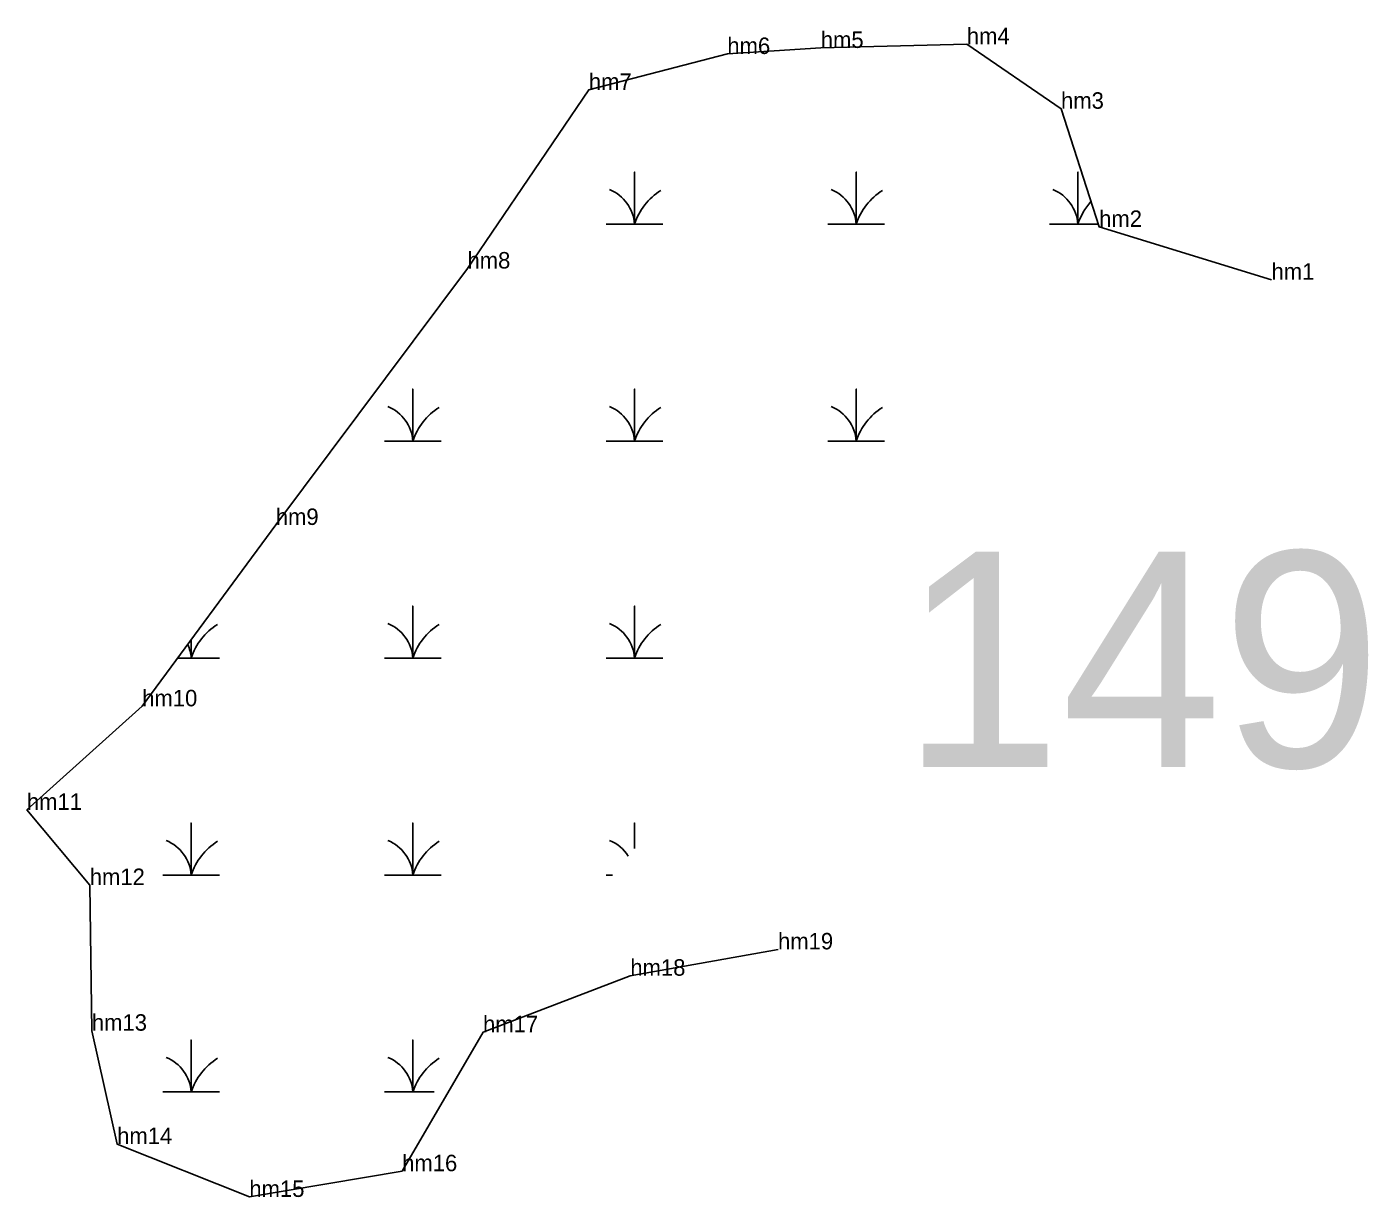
# Model space of a CAD drawing. Extents: x 2072529 to 2268796, y 436423 to 470406.
# Drawn here: x 2173124 to 2173530.9, y 447172.3 to 447527.2 of the extents above; entities that cross this region are included whole.
import ezdxf

# ---------------------------------------------------------------- set-up
doc = ezdxf.new("R2010")
doc.units = 0
for name, color, linetype in [('Default', 7, 'Continuous'), ('Exist Environmental Wetland Boundary Cogo Comment', 7, 'Continuous'), ('Exist Environmental Wetland Boundary Cogo Point CELL', 7, 'Continuous'), ('Old_Level_20', 7, 'Continuous')]:
    doc.layers.add(name, color=color, linetype=linetype)

msp = doc.modelspace()

# ---------------------------------------------------------------- linework, layer by layer
at = {"layer": 'Exist Environmental Wetland Boundary Cogo Point CELL'}
for points in [[(2173299.71, 447467.4), (2173308.31, 447467.4), (2173308.31, 447483.18), (2173308.31, 447467.4), (2173316.91, 447467.4)], [(2173366.96, 447467.4), (2173375.56, 447467.4), (2173375.56, 447483.18), (2173375.56, 447467.4), (2173384.16, 447467.4)], [(2173434.21, 447467.4), (2173442.81, 447467.4), (2173442.81, 447483.18), (2173442.81, 447467.4), (2173448.98, 447467.4)], [(2173232.46, 447401.6), (2173241.06, 447401.6), (2173241.06, 447417.38), (2173241.06, 447401.6), (2173249.66, 447401.6)], [(2173299.71, 447401.6), (2173308.31, 447401.6), (2173308.31, 447417.38), (2173308.31, 447401.6), (2173316.91, 447401.6)], [(2173366.96, 447401.6), (2173375.56, 447401.6), (2173375.56, 447417.38), (2173375.56, 447401.6), (2173384.16, 447401.6)], [(2173232.46, 447335.8), (2173241.06, 447335.8), (2173241.06, 447351.58), (2173241.06, 447335.8), (2173249.66, 447335.8)], [(2173299.71, 447335.8), (2173308.31, 447335.8), (2173308.31, 447351.58), (2173308.31, 447335.8), (2173316.91, 447335.8)], [(2173169.74, 447335.8), (2173173.81, 447335.8), (2173173.81, 447341.32)], [(2173173.81, 447341.32), (2173173.81, 447335.8), (2173182.41, 447335.8)], [(2173165.21, 447270), (2173173.81, 447270), (2173173.81, 447285.78), (2173173.81, 447270), (2173182.41, 447270)], [(2173232.46, 447270), (2173241.06, 447270), (2173241.06, 447285.78), (2173241.06, 447270), (2173249.66, 447270)], [(2173308.31, 447278.06), (2173308.31, 447285.78), (2173308.31, 447278.06)], [(2173299.71, 447270), (2173301.68, 447270)], [(2173165.21, 447204.2), (2173173.81, 447204.2), (2173173.81, 447219.98), (2173173.81, 447204.2), (2173182.41, 447204.2)], [(2173232.46, 447204.2), (2173241.06, 447204.2), (2173241.06, 447219.98), (2173241.06, 447204.2), (2173247.54, 447204.2)]]:
    msp.add_lwpolyline(points, dxfattribs=at)
for centre, radius, start, end in [((2173296.05, 447466.51), 12.3, 4.1403, 67.535), ((2173326.55, 447461.34), 19.22, 122.1274, 161.6222), ((2173363.3, 447466.51), 12.3, 4.1403, 67.535), ((2173393.8, 447461.34), 19.22, 122.1274, 161.6222), ((2173430.55, 447466.51), 12.3, 4.1403, 67.535), ((2173461.05, 447461.34), 19.22, 137.9393, 161.6222), ((2173228.8, 447400.71), 12.3, 4.1403, 67.535), ((2173259.3, 447395.54), 19.22, 122.1274, 161.6222), ((2173296.05, 447400.71), 12.3, 4.1403, 67.535), ((2173326.55, 447395.54), 19.22, 122.1274, 161.6222), ((2173363.3, 447400.71), 12.3, 4.1403, 67.535), ((2173393.8, 447395.54), 19.22, 122.1274, 161.6222), ((2173192.05, 447329.74), 19.22, 122.1274, 161.6222), ((2173228.8, 447334.91), 12.3, 4.1403, 67.535), ((2173259.3, 447329.74), 19.22, 122.1274, 161.6222), ((2173296.05, 447334.91), 12.3, 4.1403, 67.535), ((2173326.55, 447329.74), 19.22, 122.1274, 161.6222), ((2173161.55, 447334.91), 12.3, 4.1403, 24.0201), ((2173161.55, 447269.11), 12.3, 4.1403, 67.535), ((2173192.05, 447263.94), 19.22, 122.1274, 161.6222), ((2173228.8, 447269.11), 12.3, 4.1403, 67.535), ((2173259.3, 447263.94), 19.22, 122.1274, 161.6222), ((2173296.05, 447269.11), 12.3, 32.5999, 67.535), ((2173161.55, 447203.31), 12.3, 4.1403, 67.535), ((2173192.05, 447198.14), 19.22, 122.1274, 161.6222), ((2173228.8, 447203.31), 12.3, 4.1403, 67.535), ((2173259.3, 447198.14), 19.22, 122.1274, 161.6222)]:
    msp.add_arc(centre, radius, start, end, dxfattribs=at)
at = {"layer": 'Old_Level_20'}
for p, q in [((2173409.12, 447521.96), (2173409.12, 447521.96)), ((2173336.47, 447518.99), (2173336.47, 447518.99)), ((2173364.81, 447520.82), (2173364.81, 447520.82)), ((2173294.45, 447508.11), (2173294.45, 447508.11)), ((2173437.7, 447502.38), (2173437.7, 447502.38)), ((2173449.26, 447466.55), (2173449.26, 447466.55)), ((2173257.63, 447453.93), (2173257.63, 447453.93)), ((2173501.56, 447450.54), (2173501.56, 447450.54)), ((2173199.48, 447376.16), (2173199.48, 447376.16)), ((2173158.95, 447321.16), (2173158.95, 447321.16)), ((2173123.96, 447289.75), (2173123.96, 447289.75)), ((2173143.04, 447266.95), (2173143.04, 447266.95)), ((2173351.85, 447247.45), (2173351.85, 447247.45)), ((2173307.04, 447239.47), (2173307.04, 447239.47)), ((2173143.68, 447222.78), (2173143.68, 447222.78)), ((2173262.35, 447222.32), (2173262.35, 447222.32)), ((2173151.35, 447188.42), (2173151.35, 447188.42)), ((2173237.81, 447180.17), (2173237.81, 447180.17)), ((2173191.46, 447172.37), (2173191.46, 447172.37))]:
    msp.add_line(p, q, dxfattribs=at)
msp.add_lwpolyline([(2173501.56, 447450.54), (2173449.26, 447466.55), (2173437.7, 447502.38), (2173409.12, 447521.96), (2173364.81, 447520.82), (2173336.47, 447518.99), (2173294.45, 447508.11), (2173257.63, 447453.93), (2173199.48, 447376.16), (2173158.95, 447321.16), (2173123.96, 447289.75), (2173143.04, 447266.95), (2173143.68, 447222.78), (2173151.35, 447188.42), (2173191.46, 447172.37), (2173237.81, 447180.17), (2173262.35, 447222.32), (2173307.04, 447239.47), (2173351.85, 447247.45)], dxfattribs=at)

# ---------------------------------------------------------------- texts
at = {"layer": 'Default'}
msp.add_text('149', height=65.34, dxfattribs=at).set_placement((2173389.24, 447302.72))
at = {"layer": 'Exist Environmental Wetland Boundary Cogo Comment'}
for s, p in [('hm5', (2173364.81, 447520.82)), ('hm4', (2173409.12, 447521.96)), ('hm6', (2173336.47, 447518.99)), ('hm7', (2173294.45, 447508.11)), ('hm3', (2173437.7, 447502.38)), ('hm2', (2173449.26, 447466.55)), ('hm8', (2173257.63, 447453.93)), ('hm1', (2173501.56, 447450.54)), ('hm9', (2173199.48, 447376.16)), ('hm10', (2173158.95, 447321.16)), ('hm11', (2173123.96, 447289.75)), ('hm12', (2173143.04, 447266.95)), ('hm19', (2173351.85, 447247.45)), ('hm18', (2173307.04, 447239.47)), ('hm13', (2173143.68, 447222.78)), ('hm17', (2173262.35, 447222.32)), ('hm14', (2173151.35, 447188.42)), ('hm16', (2173237.81, 447180.17)), ('hm15', (2173191.46, 447172.37))]:
    msp.add_text(s, height=5, dxfattribs=at).set_placement(p)

doc.saveas('drawing.dxf')
